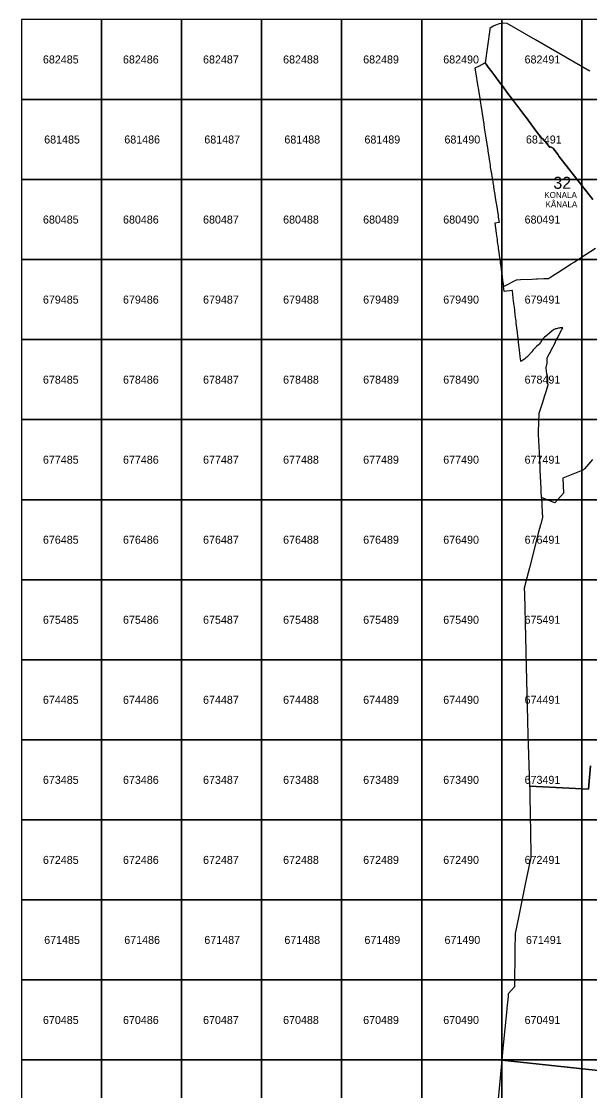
# Model space of a CAD drawing. Extents: x 25485000 to 25520000, y 6656775 to 6690000.
# Drawn here: x 25485000 to 25492097, y 6669617 to 6682976 of the extents above; entities that cross this region are included whole.
import ezdxf

# ---------------------------------------------------------------- set-up
doc = ezdxf.new("R2010")
doc.units = 0
doc.layers.add('Level 63', color=7, linetype='Continuous')

msp = doc.modelspace()

# ---------------------------------------------------------------- linework, layer by layer
at = {"layer": 'Level 63'}
for points in [[(25485000, 6682000), (25486000, 6682000), (25486000, 6683000), (25485000, 6683000)], [(25486000, 6682000), (25487000, 6682000), (25487000, 6683000), (25486000, 6683000)], [(25487000, 6682000), (25488000, 6682000), (25488000, 6683000), (25487000, 6683000)], [(25488000, 6682000), (25489000, 6682000), (25489000, 6683000), (25488000, 6683000)], [(25489000, 6682000), (25490000, 6682000), (25490000, 6683000), (25489000, 6683000)], [(25490000, 6682000), (25491000, 6682000), (25491000, 6683000), (25490000, 6683000)], [(25491000, 6682000), (25492000, 6682000), (25492000, 6683000), (25491000, 6683000)], [(25492000, 6682000), (25493000, 6682000), (25493000, 6683000), (25492000, 6683000)], [(25485000, 6681000), (25486000, 6681000), (25486000, 6682000), (25485000, 6682000)], [(25486000, 6681000), (25487000, 6681000), (25487000, 6682000), (25486000, 6682000)], [(25487000, 6681000), (25488000, 6681000), (25488000, 6682000), (25487000, 6682000)], [(25488000, 6681000), (25489000, 6681000), (25489000, 6682000), (25488000, 6682000)], [(25489000, 6681000), (25490000, 6681000), (25490000, 6682000), (25489000, 6682000)], [(25490000, 6681000), (25491000, 6681000), (25491000, 6682000), (25490000, 6682000)], [(25491000, 6681000), (25492000, 6681000), (25492000, 6682000), (25491000, 6682000)], [(25492000, 6681000), (25493000, 6681000), (25493000, 6682000), (25492000, 6682000)], [(25485000, 6680000), (25486000, 6680000), (25486000, 6681000), (25485000, 6681000)], [(25486000, 6680000), (25487000, 6680000), (25487000, 6681000), (25486000, 6681000)], [(25487000, 6680000), (25488000, 6680000), (25488000, 6681000), (25487000, 6681000)], [(25488000, 6680000), (25489000, 6680000), (25489000, 6681000), (25488000, 6681000)], [(25489000, 6680000), (25490000, 6680000), (25490000, 6681000), (25489000, 6681000)], [(25490000, 6680000), (25491000, 6680000), (25491000, 6681000), (25490000, 6681000)], [(25491000, 6680000), (25492000, 6680000), (25492000, 6681000), (25491000, 6681000)], [(25492000, 6680000), (25493000, 6680000), (25493000, 6681000), (25492000, 6681000)], [(25485000, 6679000), (25486000, 6679000), (25486000, 6680000), (25485000, 6680000)], [(25486000, 6679000), (25487000, 6679000), (25487000, 6680000), (25486000, 6680000)], [(25487000, 6679000), (25488000, 6679000), (25488000, 6680000), (25487000, 6680000)], [(25488000, 6679000), (25489000, 6679000), (25489000, 6680000), (25488000, 6680000)], [(25489000, 6679000), (25490000, 6679000), (25490000, 6680000), (25489000, 6680000)], [(25490000, 6679000), (25491000, 6679000), (25491000, 6680000), (25490000, 6680000)], [(25491000, 6679000), (25492000, 6679000), (25492000, 6680000), (25491000, 6680000)], [(25492000, 6679000), (25493000, 6679000), (25493000, 6680000), (25492000, 6680000)], [(25485000, 6678000), (25486000, 6678000), (25486000, 6679000), (25485000, 6679000)], [(25486000, 6678000), (25487000, 6678000), (25487000, 6679000), (25486000, 6679000)], [(25487000, 6678000), (25488000, 6678000), (25488000, 6679000), (25487000, 6679000)], [(25488000, 6678000), (25489000, 6678000), (25489000, 6679000), (25488000, 6679000)], [(25489000, 6678000), (25490000, 6678000), (25490000, 6679000), (25489000, 6679000)], [(25490000, 6678000), (25491000, 6678000), (25491000, 6679000), (25490000, 6679000)], [(25491000, 6678000), (25492000, 6678000), (25492000, 6679000), (25491000, 6679000)], [(25492000, 6678000), (25493000, 6678000), (25493000, 6679000), (25492000, 6679000)], [(25485000, 6677000), (25486000, 6677000), (25486000, 6678000), (25485000, 6678000)], [(25486000, 6677000), (25487000, 6677000), (25487000, 6678000), (25486000, 6678000)], [(25487000, 6677000), (25488000, 6677000), (25488000, 6678000), (25487000, 6678000)], [(25488000, 6677000), (25489000, 6677000), (25489000, 6678000), (25488000, 6678000)], [(25489000, 6677000), (25490000, 6677000), (25490000, 6678000), (25489000, 6678000)], [(25490000, 6677000), (25491000, 6677000), (25491000, 6678000), (25490000, 6678000)], [(25491000, 6677000), (25492000, 6677000), (25492000, 6678000), (25491000, 6678000)], [(25492000, 6677000), (25493000, 6677000), (25493000, 6678000), (25492000, 6678000)], [(25485000, 6676000), (25486000, 6676000), (25486000, 6677000), (25485000, 6677000)], [(25486000, 6676000), (25487000, 6676000), (25487000, 6677000), (25486000, 6677000)], [(25487000, 6676000), (25488000, 6676000), (25488000, 6677000), (25487000, 6677000)], [(25488000, 6676000), (25489000, 6676000), (25489000, 6677000), (25488000, 6677000)], [(25489000, 6676000), (25490000, 6676000), (25490000, 6677000), (25489000, 6677000)], [(25490000, 6676000), (25491000, 6676000), (25491000, 6677000), (25490000, 6677000)], [(25491000, 6676000), (25492000, 6676000), (25492000, 6677000), (25491000, 6677000)], [(25492000, 6676000), (25493000, 6676000), (25493000, 6677000), (25492000, 6677000)], [(25485000, 6675000), (25486000, 6675000), (25486000, 6676000), (25485000, 6676000)], [(25486000, 6675000), (25487000, 6675000), (25487000, 6676000), (25486000, 6676000)], [(25487000, 6675000), (25488000, 6675000), (25488000, 6676000), (25487000, 6676000)], [(25488000, 6675000), (25489000, 6675000), (25489000, 6676000), (25488000, 6676000)], [(25489000, 6675000), (25490000, 6675000), (25490000, 6676000), (25489000, 6676000)], [(25490000, 6675000), (25491000, 6675000), (25491000, 6676000), (25490000, 6676000)], [(25491000, 6675000), (25492000, 6675000), (25492000, 6676000), (25491000, 6676000)], [(25492000, 6675000), (25493000, 6675000), (25493000, 6676000), (25492000, 6676000)], [(25485000, 6674000), (25486000, 6674000), (25486000, 6675000), (25485000, 6675000)], [(25486000, 6674000), (25487000, 6674000), (25487000, 6675000), (25486000, 6675000)], [(25487000, 6674000), (25488000, 6674000), (25488000, 6675000), (25487000, 6675000)], [(25488000, 6674000), (25489000, 6674000), (25489000, 6675000), (25488000, 6675000)], [(25489000, 6674000), (25490000, 6674000), (25490000, 6675000), (25489000, 6675000)], [(25490000, 6674000), (25491000, 6674000), (25491000, 6675000), (25490000, 6675000)], [(25491000, 6674000), (25492000, 6674000), (25492000, 6675000), (25491000, 6675000)], [(25492000, 6674000), (25493000, 6674000), (25493000, 6675000), (25492000, 6675000)], [(25485000, 6673000), (25486000, 6673000), (25486000, 6674000), (25485000, 6674000)], [(25486000, 6673000), (25487000, 6673000), (25487000, 6674000), (25486000, 6674000)], [(25487000, 6673000), (25488000, 6673000), (25488000, 6674000), (25487000, 6674000)], [(25488000, 6673000), (25489000, 6673000), (25489000, 6674000), (25488000, 6674000)], [(25489000, 6673000), (25490000, 6673000), (25490000, 6674000), (25489000, 6674000)], [(25490000, 6673000), (25491000, 6673000), (25491000, 6674000), (25490000, 6674000)], [(25491000, 6673000), (25492000, 6673000), (25492000, 6674000), (25491000, 6674000)], [(25492000, 6673000), (25493000, 6673000), (25493000, 6674000), (25492000, 6674000)], [(25485000, 6672000), (25486000, 6672000), (25486000, 6673000), (25485000, 6673000)], [(25486000, 6672000), (25487000, 6672000), (25487000, 6673000), (25486000, 6673000)], [(25487000, 6672000), (25488000, 6672000), (25488000, 6673000), (25487000, 6673000)], [(25488000, 6672000), (25489000, 6672000), (25489000, 6673000), (25488000, 6673000)], [(25489000, 6672000), (25490000, 6672000), (25490000, 6673000), (25489000, 6673000)], [(25490000, 6672000), (25491000, 6672000), (25491000, 6673000), (25490000, 6673000)], [(25491000, 6672000), (25492000, 6672000), (25492000, 6673000), (25491000, 6673000)], [(25492000, 6672000), (25493000, 6672000), (25493000, 6673000), (25492000, 6673000)], [(25485000, 6671000), (25486000, 6671000), (25486000, 6672000), (25485000, 6672000)], [(25486000, 6671000), (25487000, 6671000), (25487000, 6672000), (25486000, 6672000)], [(25487000, 6671000), (25488000, 6671000), (25488000, 6672000), (25487000, 6672000)], [(25488000, 6671000), (25489000, 6671000), (25489000, 6672000), (25488000, 6672000)], [(25489000, 6671000), (25490000, 6671000), (25490000, 6672000), (25489000, 6672000)], [(25490000, 6671000), (25491000, 6671000), (25491000, 6672000), (25490000, 6672000)], [(25491000, 6671000), (25492000, 6671000), (25492000, 6672000), (25491000, 6672000)], [(25492000, 6671000), (25493000, 6671000), (25493000, 6672000), (25492000, 6672000)], [(25485000, 6670000), (25486000, 6670000), (25486000, 6671000), (25485000, 6671000)], [(25486000, 6670000), (25487000, 6670000), (25487000, 6671000), (25486000, 6671000)], [(25487000, 6670000), (25488000, 6670000), (25488000, 6671000), (25487000, 6671000)], [(25488000, 6670000), (25489000, 6670000), (25489000, 6671000), (25488000, 6671000)], [(25489000, 6670000), (25490000, 6670000), (25490000, 6671000), (25489000, 6671000)], [(25490000, 6670000), (25491000, 6670000), (25491000, 6671000), (25490000, 6671000)], [(25491000, 6670000), (25492000, 6670000), (25492000, 6671000), (25491000, 6671000)], [(25492000, 6670000), (25493000, 6670000), (25493000, 6671000), (25492000, 6671000)], [(25485000, 6669000), (25486000, 6669000), (25486000, 6670000), (25485000, 6670000)], [(25486000, 6669000), (25487000, 6669000), (25487000, 6670000), (25486000, 6670000)], [(25487000, 6669000), (25488000, 6669000), (25488000, 6670000), (25487000, 6670000)], [(25488000, 6669000), (25489000, 6669000), (25489000, 6670000), (25488000, 6670000)], [(25489000, 6669000), (25490000, 6669000), (25490000, 6670000), (25489000, 6670000)], [(25490000, 6669000), (25491000, 6669000), (25491000, 6670000), (25490000, 6670000)], [(25491000, 6669000), (25492000, 6669000), (25492000, 6670000), (25491000, 6670000)], [(25492000, 6669000), (25493000, 6669000), (25493000, 6670000), (25492000, 6670000)]]:
    msp.add_lwpolyline(points, close=True, dxfattribs=at)
for points in [[(25492101, 6682352), (25492078, 6682365), (25492073, 6682368), (25492061, 6682375), (25491984, 6682420), (25491420, 6682746), (25491282, 6682826), (25491067, 6682951), (25491015, 6682952), (25490967, 6682944), (25490920, 6682927), (25490891, 6682915), (25490850, 6682885), (25490849, 6682874), (25490791, 6682458), (25490844, 6682387), (25490864, 6682361), (25490913, 6682297), (25490968, 6682222), (25491016, 6682159), (25491065, 6682092), (25491145, 6681985), (25491185, 6681933), (25491199, 6681914), (25491286, 6681797), (25491307, 6681769), (25491419, 6681620), (25491499, 6681513), (25491508, 6681513), (25491561, 6681450), (25491599, 6681400), (25491607, 6681408), (25491642, 6681393), (25491651, 6681381), (25491706, 6681307), (25491713, 6681290), (25492000, 6680925), (25492046, 6680866), (25492139, 6680749)], [(25492139, 6680749), (25492046, 6680866), (25492000, 6680925), (25491713, 6681290), (25491706, 6681307), (25491651, 6681381), (25491642, 6681393), (25491607, 6681408), (25491599, 6681400), (25491561, 6681450), (25491508, 6681513), (25491499, 6681513), (25491419, 6681620), (25491307, 6681769), (25491286, 6681797), (25491199, 6681914), (25491185, 6681933), (25491145, 6681985), (25491065, 6682092), (25491016, 6682159), (25490968, 6682222), (25490913, 6682297), (25490864, 6682361), (25490844, 6682387), (25490791, 6682458), (25490717, 6682418), (25490665, 6682390), (25490680, 6682295), (25490684, 6682268), (25490690, 6682232), (25490701, 6682163), (25490704, 6682145), (25490708, 6682117), (25490725, 6682011), (25490733, 6681956), (25490738, 6681927), (25490775, 6681691), (25490782, 6681645), (25490789, 6681597), (25490797, 6681545), (25490824, 6681366), (25490826, 6681357), (25490850, 6681200), (25490853, 6681183), (25490855, 6681164), (25490857, 6681150), (25490864, 6681111), (25490867, 6681090), (25490870, 6681072), (25490871, 6681066), (25490875, 6681042), (25490879, 6681019), (25490882, 6681004), (25490883, 6680995), (25490887, 6680970), (25490888, 6680964), (25490892, 6680942), (25490896, 6680921), (25490897, 6680910), (25490901, 6680881), (25490905, 6680853), (25490906, 6680852), (25490908, 6680841), (25490908, 6680838), (25490908, 6680836), (25490917, 6680776), (25490926, 6680723), (25490928, 6680709), (25490953, 6680550), (25490956, 6680529), (25490966, 6680462), (25490912, 6680454), (25490929, 6680329), (25490930, 6680325), (25490934, 6680300), (25490937, 6680275), (25490941, 6680251), (25490944, 6680226), (25490948, 6680197), (25490953, 6680165), (25490956, 6680138), (25490963, 6680094), (25490968, 6680054), (25490972, 6680024), (25490973, 6680019), (25490979, 6679980), (25490982, 6679952), (25490982, 6679951), (25490984, 6679941), (25490989, 6679904), (25490991, 6679889), (25490993, 6679868), (25490999, 6679829), (25491000, 6679820), (25491005, 6679785), (25491006, 6679778), (25491014, 6679714), (25491015, 6679709), (25491017, 6679695), (25491021, 6679663), (25491071, 6679689), (25491088, 6679697), (25491133, 6679721), (25491183, 6679747), (25491233, 6679749), (25491378, 6679755), (25491432, 6679758), (25491447, 6679758), (25491527, 6679762), (25491545, 6679762), (25491584, 6679764), (25491634, 6679796), (25491700, 6679838), (25491769, 6679883), (25491866, 6679945), (25491903, 6679969), (25491945, 6679996), (25491997, 6680029), (25492172, 6680142)], [(25491021, 6679663), (25491071, 6679689), (25491088, 6679697), (25491133, 6679721), (25491183, 6679747), (25491233, 6679749), (25491378, 6679755), (25491432, 6679758), (25491447, 6679758), (25491527, 6679762), (25491545, 6679762), (25491584, 6679764), (25491634, 6679796), (25491700, 6679838), (25491769, 6679883), (25491866, 6679945), (25491903, 6679969), (25491945, 6679996), (25491997, 6680029), (25492172, 6680142)], [(25492133, 6677501), (25492084, 6677444), (25492033, 6677387), (25492021, 6677372), (25491993, 6677361), (25491762, 6677267), (25491770, 6677083), (25491663, 6676960), (25491547, 6677007), (25491497, 6677027), (25491493, 6677106), (25491491, 6677142), (25491481, 6677364), (25491479, 6677411), (25491478, 6677441), (25491460, 6677813), (25491459, 6677849), (25491467, 6678079), (25491509, 6678207), (25491538, 6678303), (25491557, 6678365), (25491575, 6678424), (25491579, 6678437), (25491577, 6678455), (25491576, 6678526), (25491564, 6678573), (25491560, 6678605), (25491554, 6678646), (25491554, 6678650), (25491565, 6678706), (25491565, 6678718), (25491566, 6678736), (25491568, 6678771), (25491572, 6678780), (25491596, 6678826), (25491615, 6678862), (25491639, 6678908), (25491643, 6678916), (25491665, 6678960), (25491671, 6678972), (25491689, 6679009), (25491699, 6679028), (25491722, 6679073), (25491751, 6679127), (25491753, 6679129), (25491754, 6679131), (25491755, 6679134), (25491763, 6679147), (25491754, 6679147), (25491742, 6679147), (25491730, 6679146), (25491718, 6679144), (25491706, 6679142), (25491695, 6679140), (25491683, 6679136), (25491672, 6679133), (25491653, 6679125), (25491640, 6679116), (25491630, 6679108), (25491595, 6679079), (25491565, 6679055), (25491561, 6679051), (25491532, 6679029), (25491525, 6679022), (25491514, 6679009), (25491502, 6678993), (25491489, 6678973), (25491482, 6678964), (25491467, 6678945), (25491458, 6678936), (25491435, 6678916), (25491421, 6678903), (25491404, 6678884), (25491401, 6678880), (25491389, 6678867), (25491386, 6678864), (25491374, 6678846), (25491328, 6678796), (25491320, 6678788), (25491311, 6678779), (25491302, 6678771), (25491283, 6678757), (25491262, 6678743), (25491238, 6678728), (25491237, 6678730), (25491236, 6678739), (25491236, 6678741), (25491234, 6678756), (25491233, 6678760), (25491231, 6678783), (25491226, 6678834), (25491223, 6678861), (25491217, 6678911), (25491214, 6678928), (25491199, 6679056), (25491197, 6679072), (25491197, 6679079), (25491196, 6679088), (25491195, 6679090), (25491188, 6679148), (25491181, 6679206), (25491179, 6679221), (25491178, 6679231), (25491175, 6679259), (25491173, 6679275), (25491167, 6679319), (25491163, 6679357), (25491162, 6679362), (25491158, 6679404), (25491155, 6679429), (25491152, 6679446), (25491147, 6679487), (25491144, 6679512), (25491144, 6679515), (25491143, 6679523), (25491138, 6679562), (25491132, 6679613), (25491029, 6679601), (25491024, 6679639), (25491021, 6679663)], [(25492133, 6677501), (25492084, 6677444), (25492033, 6677387), (25492021, 6677372), (25491993, 6677361), (25491762, 6677267), (25491770, 6677083), (25491663, 6676960), (25491547, 6677007), (25491497, 6677027), (25491497, 6677011), (25491498, 6676990), (25491499, 6676978), (25491500, 6676949), (25491501, 6676939), (25491501, 6676928), (25491502, 6676917), (25491504, 6676861), (25491506, 6676817), (25491507, 6676811), (25491508, 6676782), (25491486, 6676696), (25491483, 6676686), (25491472, 6676641), (25491456, 6676580), (25491379, 6676279), (25491345, 6676149), (25491297, 6675961), (25491287, 6675923), (25491280, 6675894), (25491282, 6675824), (25491310, 6674742), (25491323, 6674251), (25491323, 6674225), (25491327, 6674074), (25491348, 6673421), (25491840, 6673396), (25492083, 6673384), (25492107, 6673673)], [(25492107, 6673673), (25492083, 6673384), (25491840, 6673396), (25491348, 6673421), (25491349, 6673388), (25491349, 6673386), (25491349, 6673373), (25491350, 6673307), (25491350, 6673282), (25491353, 6673080), (25491361, 6672580), (25491361, 6672546), (25491362, 6672531), (25491358, 6672513), (25491354, 6672494), (25491292, 6672197), (25491212, 6671800), (25491167, 6671579), (25491165, 6671374), (25491160, 6670915), (25491081, 6670825), (25491078, 6670792), (25491065, 6670648), (25491063, 6670635), (25491015, 6670145), (25491001, 6669998), (25492634, 6669823)], [(25506580, 6668434), (25501638, 6667311), (25500576, 6667171), (25499970, 6667780), (25497407, 6670360), (25497357, 6670410), (25496638, 6670410), (25496588, 6670411), (25496587, 6669968), (25495369, 6669969), (25494290, 6669969), (25494289, 6669645), (25492634, 6669823), (25491001, 6669998), (25490933, 6669294), (25490867, 6668614), (25487917, 6665230), (25489109, 6662564), (25491530, 6657153), (25491699, 6656775), (25493980, 6658048), (25507391, 6664195)]]:
    msp.add_lwpolyline(points, dxfattribs=at)

# ---------------------------------------------------------------- texts
for s, height, p in [('682485', 100, (25485269, 6682450)), ('682486', 100, (25486269, 6682450)), ('682487', 100, (25487269, 6682450)), ('682488', 100, (25488269, 6682450)), ('682489', 100, (25489269, 6682450)), ('682490', 100, (25490269, 6682450)), ('682491', 100, (25491285, 6682450)), ('681485', 100, (25485285, 6681450)), ('681486', 100, (25486285, 6681450)), ('681487', 100, (25487285, 6681450)), ('681488', 100, (25488285, 6681450)), ('681489', 100, (25489285, 6681450)), ('681490', 100, (25490285, 6681450)), ('681491', 100, (25491302, 6681450)), ('32', 150, (25491644, 6680884)), ('KONALA', 75, (25491531, 6680770)), ('KÅNALA', 75, (25491547, 6680653)), ('680485', 100, (25485269, 6680450)), ('680486', 100, (25486269, 6680450)), ('680487', 100, (25487269, 6680450)), ('680488', 100, (25488269, 6680450)), ('680489', 100, (25489269, 6680450)), ('680490', 100, (25490269, 6680450)), ('680491', 100, (25491285, 6680450)), ('679485', 100, (25485269, 6679450)), ('679486', 100, (25486269, 6679450)), ('679487', 100, (25487269, 6679450)), ('679488', 100, (25488269, 6679450)), ('679489', 100, (25489269, 6679450)), ('679490', 100, (25490269, 6679450)), ('679491', 100, (25491285, 6679450)), ('678485', 100, (25485269, 6678450)), ('678486', 100, (25486269, 6678450)), ('678487', 100, (25487269, 6678450)), ('678488', 100, (25488269, 6678450)), ('678489', 100, (25489269, 6678450)), ('678490', 100, (25490269, 6678450)), ('678491', 100, (25491285, 6678450)), ('677485', 100, (25485269, 6677450)), ('677486', 100, (25486269, 6677450)), ('677487', 100, (25487269, 6677450)), ('677488', 100, (25488269, 6677450)), ('677489', 100, (25489269, 6677450)), ('677490', 100, (25490269, 6677450)), ('677491', 100, (25491285, 6677450)), ('676485', 100, (25485269, 6676450)), ('676486', 100, (25486269, 6676450)), ('676487', 100, (25487269, 6676450)), ('676488', 100, (25488269, 6676450)), ('676489', 100, (25489269, 6676450)), ('676490', 100, (25490269, 6676450)), ('676491', 100, (25491285, 6676450)), ('675485', 100, (25485269, 6675450)), ('675486', 100, (25486269, 6675450)), ('675487', 100, (25487269, 6675450)), ('675488', 100, (25488269, 6675450)), ('675489', 100, (25489269, 6675450)), ('675490', 100, (25490269, 6675450)), ('675491', 100, (25491285, 6675450)), ('674485', 100, (25485269, 6674450)), ('674486', 100, (25486269, 6674450)), ('674487', 100, (25487269, 6674450)), ('674488', 100, (25488269, 6674450)), ('674489', 100, (25489269, 6674450)), ('674490', 100, (25490269, 6674450)), ('674491', 100, (25491285, 6674450)), ('673485', 100, (25485269, 6673450)), ('673486', 100, (25486269, 6673450)), ('673487', 100, (25487269, 6673450)), ('673488', 100, (25488269, 6673450)), ('673489', 100, (25489269, 6673450)), ('673490', 100, (25490269, 6673450)), ('673491', 100, (25491285, 6673450)), ('672485', 100, (25485269, 6672450)), ('672486', 100, (25486269, 6672450)), ('672487', 100, (25487269, 6672450)), ('672488', 100, (25488269, 6672450)), ('672489', 100, (25489269, 6672450)), ('672490', 100, (25490269, 6672450)), ('672491', 100, (25491285, 6672450)), ('671485', 100, (25485285, 6671450)), ('671486', 100, (25486285, 6671450)), ('671487', 100, (25487285, 6671450)), ('671488', 100, (25488285, 6671450)), ('671489', 100, (25489285, 6671450)), ('671490', 100, (25490285, 6671450)), ('671491', 100, (25491302, 6671450)), ('670485', 100, (25485269, 6670450)), ('670486', 100, (25486269, 6670450)), ('670487', 100, (25487269, 6670450)), ('670488', 100, (25488269, 6670450)), ('670489', 100, (25489269, 6670450)), ('670490', 100, (25490269, 6670450)), ('670491', 100, (25491285, 6670450))]:
    msp.add_text(s, height=height, dxfattribs=at).set_placement(p)

doc.saveas('drawing.dxf')
